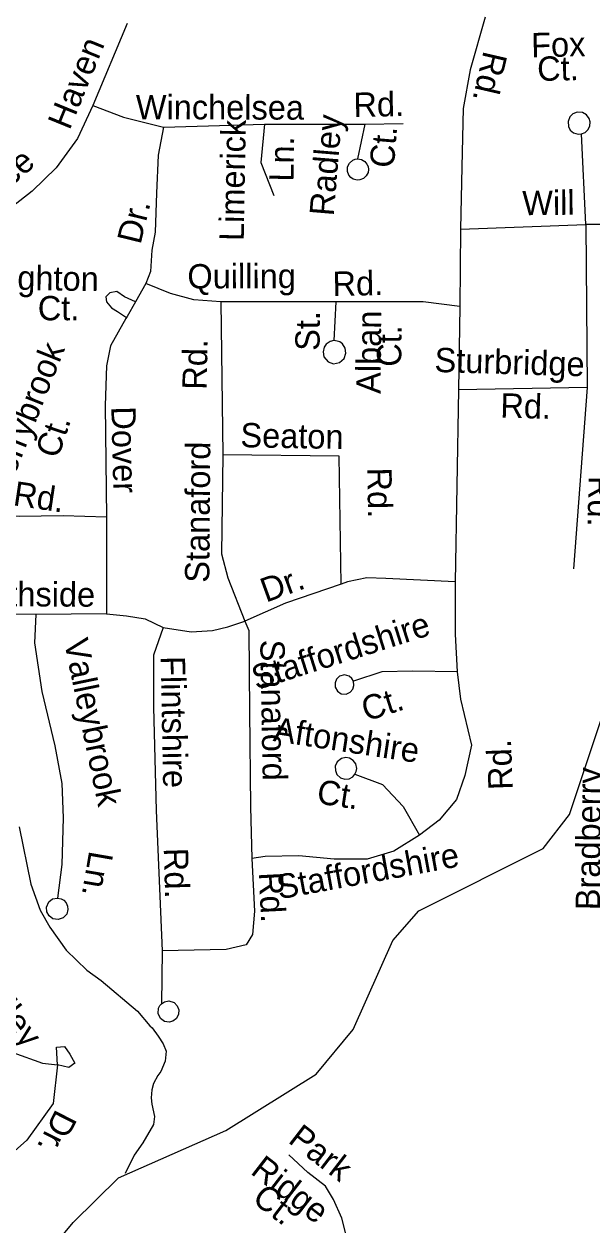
# Model space of a CAD drawing. Extents: x 1547597 to 1699558, y 810033 to 920809.
# Drawn here: x 1606161 to 1608379, y 853357 to 858046 of the extents above; entities that cross this region are included whole.
import ezdxf

# ---------------------------------------------------------------- set-up
doc = ezdxf.new("R2010")
doc.units = 0
for name, color, linetype in [('Exist Hydrographic Creek Single Shore', 7, 'Continuous'), ('Exist Hydrographic Misc Water Feature', 7, 'Continuous'), ('Exist Road Non-System Type 51', 7, 'Continuous'), ('Exist Road Non-System Type 51 Label', 7, 'Continuous')]:
    doc.layers.add(name, color=color, linetype=linetype)

msp = doc.modelspace()

# ---------------------------------------------------------------- linework, layer by layer
at = {"layer": 'Exist Hydrographic Creek Single Shore'}
msp.add_lwpolyline([(1606038.7, 852989.1), (1606352.7, 853366.9), (1606529.7, 853540.5), (1606948.7, 853725.7), (1607301.7, 853945), (1607445.7, 854119.4), (1607600.6, 854467.5), (1607702.7, 854583.6), (1608188.7, 854826.5), (1608290.6, 854959), (1608551.7, 855738.4), (1608635.6, 856406.3)], dxfattribs=at)
at = {"layer": 'Exist Hydrographic Misc Water Feature'}
msp.add_lwpolyline([(1606142.3, 854911.7), (1606187.2, 854687.1), (1606223.8, 854586.5), (1606260.9, 854520.1), (1606325.6, 854429.2), (1606406.5, 854352.1), (1606462, 854311.3), (1606604.2, 854191.4), (1606651.5, 854134.7), (1606661.3, 854126.6), (1606684.9, 854094.2), (1606704.5, 854064), (1606716, 854035.8), (1606711.5, 853995.9), (1606694.9, 853956.1), (1606682.7, 853940.3), (1606666.3, 853908.5), (1606660, 853884.7), (1606657.6, 853852.7), (1606659.2, 853828.7), (1606670.5, 853780.5), (1606666.1, 853748.5), (1606625.2, 853677.1), (1606590.6, 853629.7), (1606555.9, 853558.2)], dxfattribs=at)
at = {"layer": 'Exist Road Non-System Type 51'}
for points in [[(1607961.2, 858072.4), (1607902.9, 857867.1), (1607875.1, 857715.5), (1607870, 857488), (1607865, 857245.4)], [(1606563.5, 858048.4), (1606429.7, 857727.4)], [(1606429.7, 857727.4), (1606369, 857598.5), (1606285.7, 857484.8), (1606192.3, 857393.8), (1606053.4, 857285.1), (1605866.7, 857136.9)], [(1606429.7, 857727.4), (1606548.8, 857682.2), (1606705.3, 857642.9)], [(1608337.2, 857616.9), (1608351.9, 857622.2), (1608362.8, 857632.6), (1608370.3, 857647.2), (1608371.4, 857663.6), (1608367.9, 857677.7), (1608356.9, 857691.9), (1608341.7, 857700.7), (1608321.3, 857702.1), (1608303.4, 857694.8), (1608292.3, 857683), (1608285.2, 857665.4), (1608286.6, 857646.1), (1608294.1, 857632), (1608306.9, 857620.9), (1608324.2, 857615.4), (1608337.2, 857616.9)], [(1606705.3, 857642.9), (1606685.1, 857534.2), (1606677.5, 857385.1), (1606672.4, 857233.4), (1606659.8, 857162.7), (1606654.8, 857079.3), (1606636.4, 857032.3)], [(1606705.3, 857642.9), (1607099.3, 857654.4)], [(1607099.3, 857654.4), (1607085.6, 857505.4), (1607136.1, 857376.5)], [(1607099.3, 857654.4), (1607492.2, 857654.5)], [(1607492.2, 857654.5), (1607463.3, 857519.3)], [(1607492.2, 857654.5), (1607641.2, 857657)], [(1608354.9, 857263.1), (1608337.2, 857616.9)], [(1607463.3, 857519.3), (1607479.1, 857517.2), (1607491.1, 857509.7), (1607499.9, 857499.1), (1607504.1, 857489), (1607505.7, 857477.6), (1607504.1, 857466), (1607497.2, 857452.8), (1607486.6, 857442.6), (1607472.7, 857437.4), (1607461.1, 857436.7), (1607446.3, 857440.6), (1607436.5, 857447.2), (1607428.8, 857455.5), (1607423.7, 857470.3), (1607423.9, 857487.7), (1607431.4, 857503.1), (1607445.4, 857514.8), (1607453.3, 857518.1), (1607463.3, 857519.3)], [(1608856, 857369.1), (1608736, 857298.6), (1608622.4, 857270.8), (1608420.4, 857263.3), (1608354.9, 857263.1)], [(1607865, 857245.4), (1608354.9, 857263.1)], [(1608354.9, 857263.1), (1608359.8, 856627.3)], [(1607865, 857245.4), (1607862.3, 856943.2)], [(1606636.4, 857032.3), (1606596.3, 856961)], [(1606929.4, 856961.5), (1606823.3, 856969.1), (1606732.4, 856994.3), (1606636.4, 857032.3)], [(1606596.3, 856961), (1606553.4, 856981.2), (1606523.1, 857001.4), (1606495.3, 856996.4), (1606480.2, 856981.2), (1606482.7, 856961), (1606502.9, 856938.3), (1606525.6, 856923.1), (1606561, 856900.3)], [(1606596.3, 856961), (1606562.9, 856903.6)], [(1607378.9, 856961.5), (1607070.8, 856961.5), (1606929.4, 856961.5)], [(1606929.4, 856961.5), (1606936.9, 856363.7)], [(1607378.9, 856961.5), (1607370.6, 856809.6)], [(1607862.3, 856943.2), (1607719.8, 856961.5), (1607484.9, 856961.5), (1607378.9, 856961.5)], [(1607862.3, 856943.2), (1607857.3, 856617.2)], [(1606562.9, 856903.6), (1606558.4, 856895.9), (1606498.3, 856789.4), (1606483.2, 856711), (1606478.1, 856556.9), (1606483.2, 856120.8)], [(1607383.4, 856808.2), (1607370.6, 856809.6), (1607355.7, 856806.5), (1607341.1, 856796), (1607332.7, 856784.4), (1607328.3, 856766.5), (1607331.7, 856746), (1607349.1, 856726.6), (1607369.8, 856719.6), (1607393.1, 856724.5), (1607410.6, 856740.6), (1607417.4, 856760.8), (1607415.2, 856780.7), (1607403.8, 856797.1), (1607393.9, 856804.5), (1607383.4, 856808.2)], [(1607857.3, 856617.2), (1607844.7, 855868.2)], [(1608359.8, 856627.3), (1607857.3, 856617.2)], [(1608359.8, 856627.3), (1608306.8, 855918.7)], [(1606936.9, 856363.7), (1606931.9, 855977), (1606957.1, 855883.5), (1607022.8, 855714.2)], [(1607391.5, 856358.6), (1606936.9, 856363.7)], [(1607399.1, 855858.2), (1607391.5, 856358.6)], [(1606483.2, 856120.8), (1606314, 856125.6), (1606142.2, 856123.1), (1606046.3, 856125.6), (1605962.9, 856140.8), (1605907.4, 856173.6), (1605859.4, 856198.9)], [(1606483.2, 856120.8), (1606482.5, 855742.8)], [(1607399.1, 855858.2), (1607181.9, 855784.9), (1607022.8, 855714.2)], [(1607844.7, 855868.2), (1607573.3, 855881), (1607500.1, 855883.5), (1607424.3, 855868.3), (1607399.1, 855858.2)], [(1607844.7, 855868.2), (1607844.7, 855663.5), (1607852.3, 855516.9)], [(1606207.3, 855740.3), (1605515.1, 855742.8)], [(1606207.3, 855740.3), (1606202.2, 855629.1), (1606230, 855439.5), (1606280.5, 855227.3), (1606308.3, 855080.7), (1606313.3, 854946.7), (1606308.3, 854763.7), (1606291.7, 854632.9)], [(1606482.5, 855742.8), (1606207.3, 855740.3)], [(1606482.5, 855742.8), (1606560.7, 855735.4), (1606634, 855722.8), (1606704.7, 855689.9)], [(1606704.7, 855689.9), (1606666.8, 855581.2), (1606666.8, 855379.1), (1606676.9, 854974.7), (1606699.7, 854427.7)], [(1606704.7, 855689.9), (1606813.3, 855672.2), (1606896.6, 855677.3), (1606957.2, 855692.4), (1607022.8, 855714.2)], [(1607022.8, 855714.2), (1607038.1, 855677.3), (1607040.6, 855361.4), (1607045.6, 854989.9), (1607050, 854788.1)], [(1607440.4, 855490.1), (1607430.2, 855499.5), (1607412.1, 855504.5), (1607392.6, 855499.1), (1607381.3, 855487.7), (1607375.2, 855473), (1607375.9, 855457.2), (1607385.2, 855440.6), (1607399.8, 855431.1), (1607419.4, 855429.9), (1607434.5, 855437.2), (1607444.8, 855448.6), (1607449.3, 855463.3), (1607446.8, 855480.4), (1607440.4, 855490.1)], [(1607852.3, 855516.9), (1607678.8, 855518.5), (1607557.6, 855516), (1607446.8, 855480.4)], [(1607852.3, 855516.9), (1607864.9, 855409.8), (1607907.8, 855230.4), (1607882.6, 855111.6), (1607849.8, 855018.1), (1607781.6, 854937.2), (1607705.8, 854879.1)], [(1607452.8, 855117), (1607458, 855127.3), (1607460.5, 855139.6), (1607456.4, 855157.5), (1607446.7, 855170.9), (1607431.9, 855179.8), (1607417.1, 855182.1), (1607400.8, 855178.7), (1607383.7, 855165), (1607376.2, 855147.6), (1607376.6, 855131.1), (1607382.5, 855115.8), (1607396.9, 855102.9), (1607413.2, 855097.6), (1607430.4, 855099.2), (1607444.4, 855106.8), (1607452.8, 855117)], [(1607452.8, 855117), (1607560.1, 855076.2), (1607640.9, 854990.3), (1607705.8, 854879.1)], [(1607705.8, 854879.1), (1607604.8, 854815.9), (1607501.3, 854785.6), (1607372.5, 854785.6), (1607233.6, 854798.2), (1607103, 854795.7), (1607050, 854788.1)], [(1607050, 854788.1), (1607060.8, 854581.8), (1607053.2, 854490.8), (1607028, 854450.4), (1606949.7, 854432.7), (1606699.7, 854427.7)], [(1606291.7, 854632.9), (1606305.1, 854630.6), (1606316, 854624.8), (1606325, 854615), (1606330.9, 854602.1), (1606332.2, 854588), (1606327.5, 854570.9), (1606313.2, 854555.4), (1606293.4, 854549), (1606272.9, 854551.8), (1606258.5, 854563.1), (1606249.4, 854579.5), (1606248.2, 854597.9), (1606257.8, 854618.1), (1606272.4, 854629.7), (1606291.7, 854632.9)], [(1606699.7, 854427.7), (1606698.1, 854220.6)], [(1606698.1, 854220.6), (1606709.5, 854228.3), (1606726.6, 854231.4), (1606746.5, 854225), (1606759.2, 854212.5), (1606765.3, 854196.4), (1606764.3, 854179.2), (1606755.6, 854163.4), (1606741.6, 854152.6), (1606727.3, 854149.1), (1606709, 854151.5), (1606694.2, 854163.2), (1606684.2, 854183), (1606685.2, 854202.6), (1606691.6, 854214.1), (1606698.1, 854220.6)], [(1606034.7, 854132.6), (1606116.8, 854029.9), (1606233.1, 853988.8), (1606291.2, 853982)], [(1606291.2, 853982), (1606287.8, 854050.4), (1606318.6, 854053.9), (1606339.1, 854023), (1606359.6, 853988.8), (1606335.7, 853971.7), (1606291.2, 853982)], [(1606291.2, 853982), (1606274.1, 853831.3), (1606171.5, 853687.5), (1605908.1, 853454.7)], [(1607460.4, 853002.3), (1607449.4, 853062.5), (1607437.6, 853178.6), (1607427.6, 853280.7), (1607401.5, 853383.1), (1607368.7, 853455.8), (1607337.8, 853508.2), (1607268.8, 853561.5), (1607194.2, 853630.8)]]:
    msp.add_lwpolyline(points, dxfattribs=at)

# ---------------------------------------------------------------- texts
at = {"layer": 'Exist Road Non-System Type 51 Label'}
for s, rotation, p in [('Haven', 67.8211, (1606338.5, 857628.6)), ('Fox', 1.2316, (1608142.1, 857916)), ('Rd.', 257.0197, (1607956.2, 857944.5)), ('Ct.', 1.2316, (1608165.6, 857823.6)), ('Rd.', 1.1199, (1607448, 857683)), ('Winchelsea', 359.8387, (1606597.1, 857674.3)), ('Radley', 85.2954, (1607370, 857294.1)), ('Limerick', 88.9833, (1607018.7, 857198.2)), ('Ln.', 88.9833, (1607212.8, 857430)), ('Ct.', 85.2954, (1607604.8, 857481.8)), ('Peace', 40.8114, (1605937.3, 857261.3)), ('Will', 0.5668, (1608106.9, 857299.3)), ('Dr.', 76.2693, (1606615.3, 857182.3)), ('Leighton', 359.0871, (1605964.5, 857010.6)), ('Quilling', 0.1823, (1606798.8, 857013.4)), ('Rd.', 1.0696, (1607366.3, 856984.2)), ('Ct.', 0.0766, (1606214.4, 856889)), ('St.', 89.4764, (1607314.8, 856769.6)), ('Alban', 89.4764, (1607553, 856601.6)), ('Ct.', 89.4764, (1607633.7, 856707.5)), ('Terrybrook', 68.2489, (1606094.1, 856208.2)), ('Rd.', 88.9082, (1606873.8, 856617.3)), ('Sturbridge', 358.2977, (1607762.9, 856687.5)), ('Rd.', 358.2977, (1608019.9, 856509.8)), ('Dover', 271.3986, (1606501.4, 856552.1)), ('Ct.', 71.1883, (1606293, 856345.7)), ('Seaton', 358.9467, (1607005.2, 856393.7)), ('Stanaford', 89.5624, (1606884.1, 855864.2)), ('Rd.', 270.7191, (1607501.6, 856313.6)), ('Rd.', 351.5417, (1606114.8, 856167.4)), ('Rd.', 268.5643, (1608366.2, 856281.7)), ('Hearthside', 359.6775, (1605823.8, 855774.1)), ('Dr.', 20.0073, (1607105.6, 855786.2)), ('Staffordshire', 17.5618, (1607067.9, 855444.7)), ('Valleybrook', 281.6697, (1606316.3, 855635.9)), ('Stanaford', 271.0006, (1607083.2, 855641.3)), ('Flintshire', 271.0767, (1606694.5, 855577.2)), ('Ct.', 17.5618, (1607496.8, 855322.2)), ('Aftonshire', 351.3397, (1607131, 855246.7)), ('Rd.', 92.0297, (1608069.4, 855057)), ('Bradberry', 89.3021, (1608409.4, 854585.4)), ('Ct.', 351.3397, (1607300.3, 855003.4)), ('Staffordshire', 10.3523, (1607157.1, 854627.9)), ('Ln.', 260.2682, (1606415.7, 854820.8)), ('Rd.', 271.7029, (1606706.2, 854827.7)), ('Rd.', 272.9593, (1607077.1, 854732.6)), ('Valley', 307.9439, (1605950, 854314.1)), ('Dr.', 242.9648, (1606285.9, 853812.6)), ('Park', 322.3364, (1607188, 853681.2)), ('Ridge', 322.3364, (1607041.2, 853559.4)), ('Ct.', 322.3364, (1607047, 853449.7))]:
    msp.add_text(s, height=95, rotation=rotation, dxfattribs=at).set_placement(p)

doc.saveas('drawing.dxf')
